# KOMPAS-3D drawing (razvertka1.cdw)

Referenced files in C:\Мои документы\Рабочие документы\курсовик\: развертка.cdw
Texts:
  Шпиндель в сборе
  125 1 126 1 127 1 128 0 50 1|SPDS|125 1 126 1 127 1 128 0 50 1
  129 1 130 1 131 1 132 0 50 1|SPDS|129 1 130 1 131 1 132 0 50 1
  Шереметьев Н
  Давыденко П.А.
  ИМПБд-01-17
Dimensions and other numbers on the sheet: 1; 2; 3; 4; 5; 6; 7; 8; 9; 10; 11; 12; 13; 14; 15; 1:1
